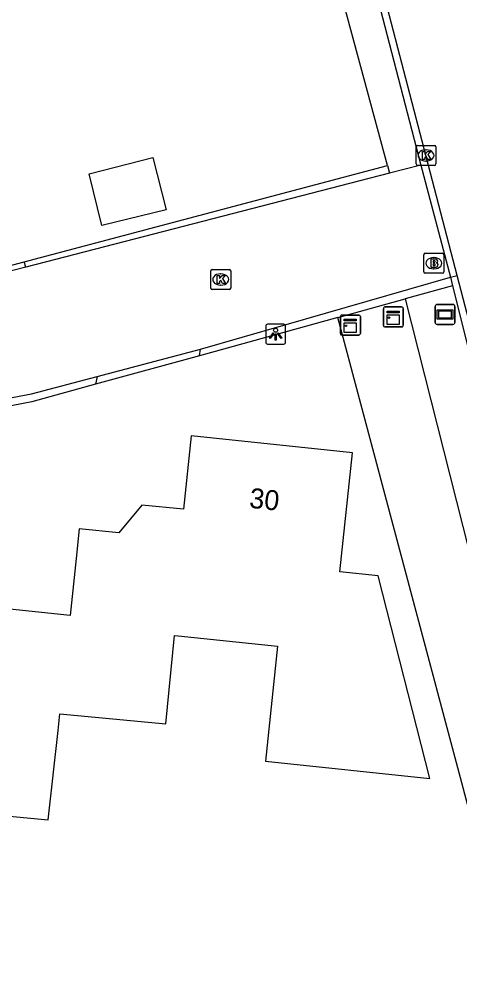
# Model space of a CAD drawing. Extents: x 162157 to 163165, y 378998 to 380775.
# Drawn here: x 162635.68 to 162657.78, y 380504.1 to 380551.95 of the extents above; entities that cross this region are included whole.
import ezdxf

# ---------------------------------------------------------------- set-up
doc = ezdxf.new("R2010")
doc.units = 0
for name, color, linetype in [('IMGEO_Brandkraan', 7, 'Continuous'), ('IMGEO_Groenvoorziening', 7, 'Continuous'), ('IMGEO_Kast', 7, 'Continuous'), ('IMGEO_Kolk', 7, 'Continuous'), ('IMGEO_Lichtpunt', 7, 'Continuous'), ('IMGEO_Pand', 7, 'Continuous'), ('IMGEO_Pand_nummerreeks', 7, 'Continuous'), ('IMGEO_Rijbaan_lokaal_gesloten', 7, 'Continuous'), ('IMGEO_Rijbaan_lokaal_open', 7, 'Continuous'), ('IMGEO_Straatnaambord', 7, 'Continuous'), ('IMGEO_Voetpad_open', 7, 'Continuous')]:
    doc.layers.add(name, color=color, linetype=linetype)

msp = doc.modelspace()

# ---------------------------------------------------------------- linework, layer by layer
at = {"layer": 'IMGEO_Brandkraan'}
for p, q in [((162655.97, 380539.3), (162655.97, 380540.152)), ((162656.045, 380540.226), (162656.897, 380540.226)), ((162656.458, 380540.006), (162656.483, 380540.006)), ((162656.971, 380540.152), (162656.971, 380539.3)), ((162656.481, 380539.446), (162656.456, 380539.446)), ((162656.897, 380539.226), (162656.045, 380539.226))]:
    msp.add_line(p, q, dxfattribs=at)
for points in [[(162655.97, 380539.3), (162655.97, 380540.152)], [(162656.045, 380540.226), (162656.897, 380540.226)], [(162656.318, 380539.926), (162656.318, 380539.526), (162656.531, 380539.526)], [(162656.549, 380539.926), (162656.318, 380539.926)], [(162656.497, 380539.845), (162656.443, 380539.845), (162656.443, 380539.769)], [(162656.443, 380539.769), (162656.496, 380539.769)], [(162656.971, 380540.152), (162656.971, 380539.3)], [(162656.505, 380539.693), (162656.443, 380539.693), (162656.443, 380539.612)], [(162656.443, 380539.612), (162656.505, 380539.612)], [(162656.897, 380539.226), (162656.045, 380539.226)]]:
    msp.add_lwpolyline(points, dxfattribs=at)
for centre, radius, start, end in [((162656.047, 380540.15), 0.0765, 91.552, 178.448), ((162656.047, 380540.15), 0.0765, 91.552, 178.448), ((162656.498, 380539.807), 0.0379, 267.8285, 90.9355), ((162656.553, 380539.781), 0.145, 59.4692, 91.5367), ((162656.578, 380539.828), 0.0922, 285.5137, 58.1501), ((162656.895, 380540.15), 0.0765, 1.552, 88.448), ((162656.895, 380540.15), 0.0765, 1.552, 88.448), ((162656.047, 380539.302), 0.0765, 181.552, 268.448), ((162656.047, 380539.302), 0.0765, 181.552, 268.448), ((162656.506, 380539.652), 0.0404, 269.8759, 90.5077), ((162656.537, 380539.777), 0.251, 268.6676, 293.5347), ((162656.583, 380539.636), 0.105, 301.3115, 78.989), ((162656.895, 380539.302), 0.0765, 271.552, 358.448), ((162656.895, 380539.302), 0.0765, 271.552, 358.448)]:
    msp.add_arc(centre, radius, start, end, dxfattribs=at)
for centre, major_axis, ratio, start_param, end_param in [((162656.457, 380539.726), (-0.387, 0.002), 0.722429, 4.712389, 7.853982), ((162656.482, 380539.726), (-0.39, 0.002), 0.717154, 1.570796, 4.712389)]:
    msp.add_ellipse(centre, major_axis=major_axis, ratio=ratio, start_param=start_param, end_param=end_param, dxfattribs=at)
at = {"layer": 'IMGEO_Groenvoorziening'}
for points in [[(162655.034, 380537.94), (162664.661, 380500), (162670.147, 380478.375)], [(162667.543, 380477.694), (162661.54, 380500), (162651.656, 380537.009)]]:
    msp.add_lwpolyline(points, dxfattribs=at)
at = {"layer": 'IMGEO_Kast'}
for p, q in [((162653.942, 380536.61), (162653.942, 380537.451)), ((162653.942, 380537.451), (162653.942, 380536.61)), ((162654.017, 380537.535), (162654.858, 380537.535)), ((162654.858, 380537.535), (162654.017, 380537.535)), ((162654.942, 380537.46), (162654.942, 380536.619)), ((162654.942, 380536.619), (162654.942, 380537.46)), ((162651.789, 380536.205), (162651.789, 380537.046)), ((162651.789, 380537.046), (162651.789, 380536.205)), ((162651.864, 380537.13), (162652.705, 380537.13)), ((162652.705, 380537.13), (162651.864, 380537.13)), ((162652.789, 380537.055), (162652.789, 380536.214)), ((162652.789, 380536.214), (162652.789, 380537.055)), ((162654.867, 380536.535), (162654.026, 380536.535)), ((162654.026, 380536.535), (162654.867, 380536.535)), ((162652.714, 380536.13), (162651.873, 380536.13)), ((162651.873, 380536.13), (162652.714, 380536.13))]:
    msp.add_line(p, q, dxfattribs=at)
for points in [[(162651.984, 380536.92), (162652.584, 380536.92), (162652.584, 380536.835), (162651.984, 380536.835), (162651.984, 380536.92)], [(162654.137, 380537.325), (162654.737, 380537.325), (162654.737, 380537.24), (162654.137, 380537.24), (162654.137, 380537.325)], [(162654.137, 380537.15), (162654.737, 380537.15), (162654.737, 380536.661), (162654.137, 380536.661), (162654.137, 380537.15)], [(162651.984, 380536.745), (162652.584, 380536.745), (162652.584, 380536.256), (162651.984, 380536.256), (162651.984, 380536.745)]]:
    msp.add_lwpolyline(points, dxfattribs=at)
for centre in [(162654.221, 380536.999), (162652.068, 380536.594)]:
    msp.add_circle(centre, 0.0377, dxfattribs=at)
for centre, start, end in [((162654.02, 380537.457), 92.4484, 184.2845), ((162654.02, 380537.457), 92.4484, 184.2845), ((162654.864, 380537.457), 2.4484, 94.2845), ((162654.864, 380537.457), 2.4484, 94.2845), ((162651.867, 380537.052), 92.4484, 184.2845), ((162651.867, 380537.052), 92.4484, 184.2845), ((162652.711, 380537.052), 2.4484, 94.2845), ((162652.711, 380537.052), 2.4484, 94.2845), ((162654.02, 380536.613), 182.4484, 274.2845), ((162654.02, 380536.613), 182.4484, 274.2845), ((162654.864, 380536.613), 272.4484, 4.2845), ((162654.864, 380536.613), 272.4484, 4.2845), ((162651.867, 380536.208), 182.4484, 274.2845), ((162651.867, 380536.208), 182.4484, 274.2845), ((162652.711, 380536.208), 272.4484, 4.2845), ((162652.711, 380536.208), 272.4484, 4.2845)]:
    msp.add_arc(centre, 0.0779, start, end, dxfattribs=at)
at = {"layer": 'IMGEO_Kolk'}
for p, q in [((162655.579, 380544.695), (162655.579, 380545.547)), ((162655.654, 380545.621), (162656.506, 380545.621)), ((162656.58, 380545.547), (162656.58, 380544.695)), ((162656.067, 380545.401), (162656.092, 380545.401)), ((162656.506, 380544.621), (162655.654, 380544.621)), ((162656.09, 380544.841), (162656.065, 380544.841)), ((162645.288, 380538.485), (162645.288, 380539.337)), ((162645.363, 380539.411), (162646.215, 380539.411)), ((162646.289, 380539.337), (162646.289, 380538.485)), ((162645.776, 380539.191), (162645.801, 380539.191)), ((162646.215, 380538.411), (162645.363, 380538.411)), ((162645.799, 380538.631), (162645.774, 380538.631))]:
    msp.add_line(p, q, dxfattribs=at)
for points in [[(162655.579, 380544.695), (162655.579, 380545.547)], [(162655.654, 380545.621), (162656.506, 380545.621)], [(162656.58, 380545.547), (162656.58, 380544.695)], [(162655.9, 380545.321), (162656.023, 380545.321), (162656.023, 380545.17), (162656.153, 380545.321), (162656.317, 380545.321), (162656.171, 380545.17), (162656.324, 380544.921), (162656.172, 380544.921), (162656.087, 380545.085), (162656.023, 380545.018), (162656.023, 380544.921), (162655.9, 380544.921), (162655.9, 380545.321)], [(162656.506, 380544.621), (162655.654, 380544.621)], [(162645.288, 380538.485), (162645.288, 380539.337)], [(162645.363, 380539.411), (162646.215, 380539.411)], [(162646.289, 380539.337), (162646.289, 380538.485)], [(162645.609, 380539.111), (162645.732, 380539.111), (162645.732, 380538.96), (162645.862, 380539.111), (162646.026, 380539.111), (162645.88, 380538.96), (162646.033, 380538.711), (162645.881, 380538.711), (162645.796, 380538.875), (162645.732, 380538.808), (162645.732, 380538.711), (162645.609, 380538.711), (162645.609, 380539.111)], [(162646.215, 380538.411), (162645.363, 380538.411)]]:
    msp.add_lwpolyline(points, dxfattribs=at)
for centre, start, end in [((162655.656, 380545.545), 91.552, 178.448), ((162655.656, 380545.545), 91.552, 178.448), ((162656.504, 380545.545), 1.552, 88.448), ((162656.504, 380545.545), 1.552, 88.448), ((162655.656, 380544.697), 181.552, 268.448), ((162655.656, 380544.697), 181.552, 268.448), ((162656.504, 380544.697), 271.552, 358.448), ((162656.504, 380544.697), 271.552, 358.448), ((162645.365, 380539.335), 91.552, 178.448), ((162645.365, 380539.335), 91.552, 178.448), ((162646.213, 380539.335), 1.552, 88.448), ((162646.213, 380539.335), 1.552, 88.448), ((162645.365, 380538.487), 181.552, 268.448), ((162645.365, 380538.487), 181.552, 268.448), ((162646.213, 380538.487), 271.552, 358.448), ((162646.213, 380538.487), 271.552, 358.448)]:
    msp.add_arc(centre, 0.0765, start, end, dxfattribs=at)
for centre, major_axis, ratio, start_param, end_param in [((162656.066, 380545.121), (-0.387, 0.002), 0.722429, 4.712389, 7.853982), ((162656.091, 380545.121), (-0.39, 0.002), 0.717154, 1.570796, 4.712389), ((162645.775, 380538.911), (-0.387, 0.002), 0.722429, 4.712389, 7.853982), ((162645.8, 380538.911), (-0.39, 0.002), 0.717154, 1.570796, 4.712389)]:
    msp.add_ellipse(centre, major_axis=major_axis, ratio=ratio, start_param=start_param, end_param=end_param, dxfattribs=at)
at = {"layer": 'IMGEO_Lichtpunt'}
for p, q in [((162648.044, 380536.577), (162648.044, 380535.77)), ((162648.044, 380536.577), (162648.044, 380535.77)), ((162648.946, 380536.672), (162648.138, 380536.672)), ((162648.946, 380536.672), (162648.138, 380536.672)), ((162649.04, 380535.77), (162649.04, 380536.577)), ((162649.04, 380535.77), (162649.04, 380536.577)), ((162648.138, 380535.676), (162648.946, 380535.676)), ((162648.138, 380535.676), (162648.946, 380535.676))]:
    msp.add_line(p, q, dxfattribs=at)
for points in [[(162648.418, 380536.241), (162648.457, 380536.213), (162648.269, 380535.951), (162648.231, 380535.978), (162648.418, 380536.241)], [(162648.52, 380536.193), (162648.567, 380536.193), (162648.567, 380535.871), (162648.52, 380535.871), (162648.52, 380536.193)], [(162648.63, 380536.213), (162648.668, 380536.24), (162648.855, 380535.978), (162648.816, 380535.95), (162648.63, 380536.213)]]:
    msp.add_lwpolyline(points, dxfattribs=at)
msp.add_circle((162648.543, 380536.375), 0.0994, dxfattribs=at)
for centre, start, end in [((162648.138, 380536.577), 90, 180), ((162648.138, 380536.577), 90, 180), ((162648.946, 380536.577), 0, 90), ((162648.946, 380536.577), 0, 90), ((162648.138, 380535.77), 180, 270), ((162648.138, 380535.77), 180, 270), ((162648.946, 380535.77), 270, 0), ((162648.946, 380535.77), 270, 360)]:
    msp.add_arc(centre, 0.0946, start, end, dxfattribs=at)
at = {"layer": 'IMGEO_Pand'}
for points in [[(162642.384, 380545.021), (162643.06, 380542.394), (162639.825, 380541.608), (162639.194, 380544.2), (162642.384, 380545.021)], [(162634.139, 380512.149), (162637.133, 380511.867), (162637.637, 380516.338), (162637.725, 380517.166), (162643.047, 380516.664), (162643.465, 380521.099), (162643.657, 380521.079), (162648.633, 380520.554), (162648.027, 380514.809), (162656.269, 380513.94), (162653.68, 380524.072), (162651.767, 380524.274), (162652.396, 380530.238), (162644.312, 380531.09), (162643.924, 380527.412), (162641.839, 380527.617), (162640.684, 380526.225), (162638.702, 380526.428), (162638.545, 380524.941), (162638.245, 380522.092), (162635.226, 380522.41), (162634.78, 380518.202)]]:
    msp.add_lwpolyline(points, dxfattribs=at)
at = {"layer": 'IMGEO_Rijbaan_lokaal_gesloten'}
for points in [[(162657.649, 380539.117), (162650.238, 380567.497)], [(162650.166, 380566.381), (162655.824, 380544.641)], [(162655.824, 380544.641), (162657.309, 380539.028)], [(162657.309, 380539.028), (162657.649, 380539.117)], [(162657.309, 380539.028), (162657.416, 380538.596)], [(162678.535, 380447.716), (162678.253, 380450.55), (162677.316, 380459.965), (162676.381, 380466.512), (162675.002, 380472.733), (162670.658, 380489.297), (162667.863, 380500), (162657.649, 380539.117)], [(162657.416, 380538.596), (162660.655, 380525.668), (162667.446, 380500), (162672.577, 380480.608)]]:
    msp.add_lwpolyline(points, dxfattribs=at)
at = {"layer": 'IMGEO_Rijbaan_lokaal_open'}
for points in [[(162635.932, 380539.794), (162654.148, 380544.616)], [(162654.148, 380544.616), (162654.251, 380544.234)], [(162655.824, 380544.641), (162654.251, 380544.234)], [(162654.251, 380544.234), (162636.02, 380539.523)], [(162636.02, 380539.523), (162635.932, 380539.794)], [(162636.02, 380539.523), (162633.725, 380538.944)], [(162644.772, 380535.432), (162657.309, 380539.028)], [(162657.416, 380538.596), (162655.034, 380537.94)], [(162651.656, 380537.009), (162655.034, 380537.94)], [(162651.656, 380537.009), (162644.718, 380535.098)], [(162639.602, 380534.061), (162644.772, 380535.432)], [(162644.718, 380535.098), (162644.772, 380535.432)], [(162633.38, 380532.64), (162636.311, 380533.188), (162639.602, 380534.061)], [(162639.602, 380534.061), (162639.517, 380533.665)], [(162639.517, 380533.665), (162636.325, 380532.786), (162633.372, 380532.22)]]:
    msp.add_lwpolyline(points, dxfattribs=at)
at = {"layer": 'IMGEO_Straatnaambord'}
for p, q in [((162656.538, 380536.763), (162656.538, 380537.563)), ((162656.538, 380537.563), (162656.538, 380536.763)), ((162656.638, 380537.663), (162657.428, 380537.663)), ((162657.428, 380537.663), (162656.638, 380537.663)), ((162657.528, 380537.563), (162657.528, 380536.763)), ((162657.528, 380536.763), (162657.528, 380537.563)), ((162657.428, 380536.663), (162656.638, 380536.663)), ((162656.638, 380536.663), (162657.428, 380536.663))]:
    msp.add_line(p, q, dxfattribs=at)
for points in [[(162656.639, 380537.395), (162657.427, 380537.395), (162657.427, 380536.931), (162656.639, 380536.931), (162656.639, 380537.395)], [(162656.704, 380537.33), (162656.704, 380536.996), (162657.362, 380536.996), (162657.362, 380537.33), (162656.704, 380537.33)]]:
    msp.add_lwpolyline(points, dxfattribs=at)
for centre, start, end in [((162656.638, 380537.563), 90, 180), ((162656.638, 380537.563), 90, 180), ((162657.428, 380537.563), 0, 90), ((162657.428, 380537.563), 360, 90), ((162656.638, 380536.763), 180, 270), ((162656.638, 380536.763), 180, 270), ((162657.428, 380536.763), 270, 0), ((162657.428, 380536.763), 270, 0)]:
    msp.add_arc(centre, 0.1, start, end, dxfattribs=at)
at = {"layer": 'IMGEO_Voetpad_open'}
for points in [[(162654.148, 380544.616), (162648.088, 380567.05), (162647.078, 380570.219), (162645.238, 380574.709), (162641.879, 380580.728)], [(162633.595, 380539.175), (162635.932, 380539.794)], [(162644.718, 380535.098), (162639.517, 380533.665)]]:
    msp.add_lwpolyline(points, dxfattribs=at)

# ---------------------------------------------------------------- texts
at = {"layer": 'IMGEO_Pand_nummerreeks'}
msp.add_text('30', height=1, rotation=353.9839, dxfattribs=at).set_placement((162647.192, 380527.489))

doc.saveas('drawing.dxf')
